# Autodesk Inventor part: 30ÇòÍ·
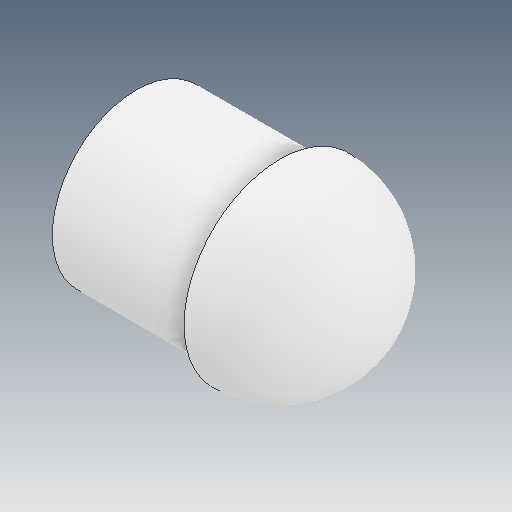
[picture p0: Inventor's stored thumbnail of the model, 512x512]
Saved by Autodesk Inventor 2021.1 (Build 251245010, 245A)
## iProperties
Created: 2021-05
Part Number: 30ÇòÍ·
Material: Ogólny
Document SubType Name: Modeling
Designer: user
Density: 1 g/cm^3
Appearance: Domyślna
Author: user
Revision Number: ÈÎºÎ
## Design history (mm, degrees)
feature "ÊäÈë1"
node "Bryła1"
